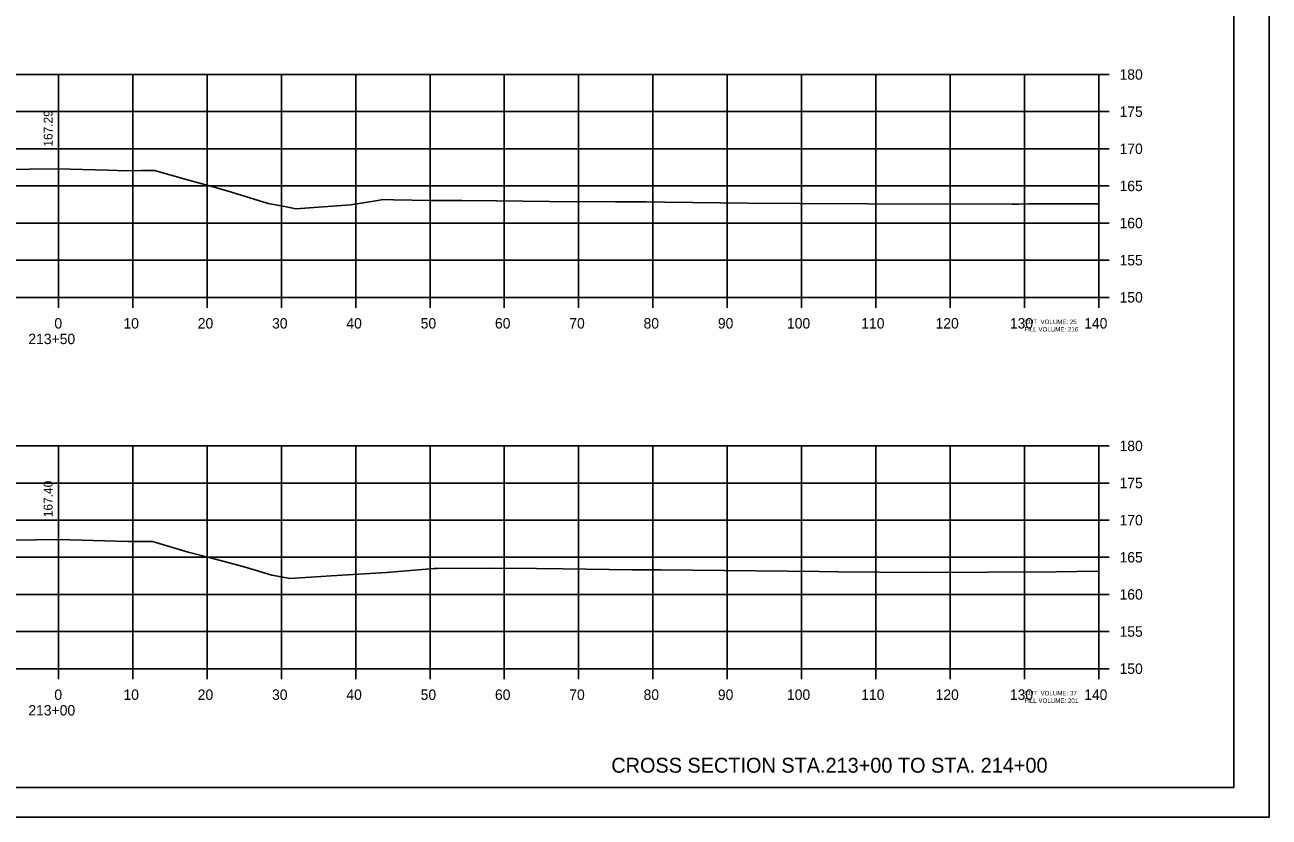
# Model space of a CAD drawing. Extents: x 1368503 to 1373085, y 379840 to 381833.
# Drawn here: x 1368668.5 to 1368836, y 381192.7 to 381299.4 of the extents above; entities that cross this region are included whole.
import ezdxf

# ---------------------------------------------------------------- set-up
doc = ezdxf.new("R2010")
doc.units = 0
for name, color, linetype in [('S_BRIDGE', 7, 'Continuous'), ('S_EDGE_PAVEMENT', 7, 'Continuous'), ('S_MISC_BOUNDARY', 7, 'Continuous'), ('S_PHOTO_CENTERS', 7, 'Continuous'), ('S_PHOTO_NOTES', 7, 'Continuous'), ('S_TRAILS', 7, 'Continuous'), ('S_TRAILS_ANNOT', 7, 'Continuous'), ('S_TREE', 7, 'Continuous')]:
    doc.layers.add(name, color=color, linetype=linetype)

msp = doc.modelspace()

# ---------------------------------------------------------------- linework, layer by layer
at = {"layer": 'S_BRIDGE'}
for q in [(1368831.24, 381402.18), (1368515.06, 381196.72)]:
    msp.add_line((1368831.24, 381196.72), q, dxfattribs=at)
at = {"layer": 'S_EDGE_PAVEMENT'}
for p, q in [((1368813.06, 381262.72), (1368813.06, 381292.72)), ((1368814.46, 381292.72), (1368813.06, 381292.72)), ((1368814.46, 381287.72), (1368813.06, 381287.72)), ((1368814.46, 381282.72), (1368813.06, 381282.72)), ((1368814.46, 381277.72), (1368813.06, 381277.72)), ((1368814.46, 381272.72), (1368813.06, 381272.72)), ((1368814.46, 381267.72), (1368813.06, 381267.72)), ((1368533.06, 381262.72), (1368813.06, 381262.72)), ((1368673.06, 381261.32), (1368673.06, 381262.72)), ((1368683.06, 381261.32), (1368683.06, 381262.72)), ((1368693.06, 381261.32), (1368693.06, 381262.72)), ((1368703.06, 381261.32), (1368703.06, 381262.72)), ((1368713.06, 381261.32), (1368713.06, 381262.72)), ((1368723.06, 381261.32), (1368723.06, 381262.72)), ((1368733.06, 381261.32), (1368733.06, 381262.72)), ((1368743.06, 381261.32), (1368743.06, 381262.72)), ((1368753.06, 381261.32), (1368753.06, 381262.72)), ((1368763.06, 381261.32), (1368763.06, 381262.72)), ((1368773.06, 381261.32), (1368773.06, 381262.72)), ((1368783.06, 381261.32), (1368783.06, 381262.72)), ((1368793.06, 381261.32), (1368793.06, 381262.72)), ((1368803.06, 381261.32), (1368803.06, 381262.72)), ((1368813.06, 381261.32), (1368813.06, 381262.72)), ((1368814.46, 381262.72), (1368813.06, 381262.72)), ((1368813.06, 381212.72), (1368813.06, 381242.72)), ((1368814.46, 381242.72), (1368813.06, 381242.72)), ((1368814.46, 381237.72), (1368813.06, 381237.72)), ((1368814.46, 381232.72), (1368813.06, 381232.72)), ((1368814.46, 381227.72), (1368813.06, 381227.72)), ((1368814.46, 381222.72), (1368813.06, 381222.72)), ((1368814.46, 381217.72), (1368813.06, 381217.72)), ((1368533.06, 381212.72), (1368813.06, 381212.72)), ((1368673.06, 381211.32), (1368673.06, 381212.72)), ((1368683.06, 381211.32), (1368683.06, 381212.72)), ((1368693.06, 381211.32), (1368693.06, 381212.72)), ((1368703.06, 381211.32), (1368703.06, 381212.72)), ((1368713.06, 381211.32), (1368713.06, 381212.72)), ((1368723.06, 381211.32), (1368723.06, 381212.72)), ((1368733.06, 381211.32), (1368733.06, 381212.72)), ((1368743.06, 381211.32), (1368743.06, 381212.72)), ((1368753.06, 381211.32), (1368753.06, 381212.72)), ((1368763.06, 381211.32), (1368763.06, 381212.72)), ((1368773.06, 381211.32), (1368773.06, 381212.72)), ((1368783.06, 381211.32), (1368783.06, 381212.72)), ((1368793.06, 381211.32), (1368793.06, 381212.72)), ((1368803.06, 381211.32), (1368803.06, 381212.72)), ((1368813.06, 381211.32), (1368813.06, 381212.72)), ((1368814.46, 381212.72), (1368813.06, 381212.72))]:
    msp.add_line(p, q, dxfattribs=at)
at = {"layer": 'S_MISC_BOUNDARY'}
for points in [[(1368665.26, 381279.95), (1368672.95, 381280.01), (1368679.64, 381279.84), (1368682.25, 381279.77), (1368684.17, 381279.79), (1368685.98, 381279.78), (1368690.43, 381278.56), (1368693.89, 381277.61), (1368696.33, 381276.87), (1368701.27, 381275.34), (1368703.5, 381274.93), (1368705.01, 381274.65), (1368708.05, 381274.86), (1368712.42, 381275.18), (1368716.02, 381275.78), (1368716.69, 381275.9), (1368718.18, 381275.86), (1368723.09, 381275.77), (1368727.32, 381275.75), (1368732.04, 381275.71), (1368739.13, 381275.62), (1368748.01, 381275.57), (1368750.79, 381275.59), (1368752.12, 381275.58), (1368754.66, 381275.55), (1368765.83, 381275.42), (1368772.82, 381275.37), (1368781.92, 381275.3), (1368801.47, 381275.28), (1368802.28, 381275.28), (1368803.59, 381275.29), (1368813.06, 381275.32)], [(1368664.11, 381229.98), (1368672.82, 381230.13), (1368674.64, 381230.08), (1368682.38, 381229.86), (1368683.53, 381229.84), (1368685.72, 381229.86), (1368690.53, 381228.43), (1368693.5, 381227.64), (1368698.03, 381226.42), (1368701.77, 381225.33), (1368703.51, 381224.99), (1368704.21, 381224.86), (1368709.76, 381225.23), (1368717.19, 381225.67), (1368723.61, 381226.19), (1368723.83, 381226.21), (1368724.05, 381226.22), (1368730.95, 381226.27), (1368737.38, 381226.23), (1368741, 381226.17), (1368750.26, 381226.04), (1368754.13, 381226.02), (1368775.45, 381225.8), (1368778.02, 381225.78), (1368789.03, 381225.67), (1368798.07, 381225.7), (1368807.32, 381225.74), (1368812.89, 381225.83), (1368813.06, 381225.83)]]:
    msp.add_lwpolyline(points, dxfattribs=at)
at = {"layer": 'S_PHOTO_CENTERS'}
for p, q in [((1368533.06, 381292.72), (1368813.06, 381292.72)), ((1368673.06, 381262.72), (1368673.06, 381292.72)), ((1368683.06, 381262.72), (1368683.06, 381292.72)), ((1368693.06, 381262.72), (1368693.06, 381292.72)), ((1368703.06, 381262.72), (1368703.06, 381292.72)), ((1368713.06, 381262.72), (1368713.06, 381292.72)), ((1368723.06, 381262.72), (1368723.06, 381292.72)), ((1368733.06, 381262.72), (1368733.06, 381292.72)), ((1368743.06, 381262.72), (1368743.06, 381292.72)), ((1368753.06, 381262.72), (1368753.06, 381292.72)), ((1368763.06, 381262.72), (1368763.06, 381292.72)), ((1368773.06, 381262.72), (1368773.06, 381292.72)), ((1368783.06, 381262.72), (1368783.06, 381292.72)), ((1368793.06, 381262.72), (1368793.06, 381292.72)), ((1368803.06, 381262.72), (1368803.06, 381292.72)), ((1368813.06, 381262.72), (1368813.06, 381292.72)), ((1368533.06, 381287.72), (1368813.06, 381287.72)), ((1368533.06, 381282.72), (1368813.06, 381282.72)), ((1368533.06, 381277.72), (1368813.06, 381277.72)), ((1368533.06, 381272.72), (1368813.06, 381272.72)), ((1368533.06, 381267.72), (1368813.06, 381267.72)), ((1368533.06, 381262.72), (1368813.06, 381262.72)), ((1368533.06, 381242.72), (1368813.06, 381242.72)), ((1368673.06, 381212.72), (1368673.06, 381242.72)), ((1368683.06, 381212.72), (1368683.06, 381242.72)), ((1368693.06, 381212.72), (1368693.06, 381242.72)), ((1368703.06, 381212.72), (1368703.06, 381242.72)), ((1368713.06, 381212.72), (1368713.06, 381242.72)), ((1368723.06, 381212.72), (1368723.06, 381242.72)), ((1368733.06, 381212.72), (1368733.06, 381242.72)), ((1368743.06, 381212.72), (1368743.06, 381242.72)), ((1368753.06, 381212.72), (1368753.06, 381242.72)), ((1368763.06, 381212.72), (1368763.06, 381242.72)), ((1368773.06, 381212.72), (1368773.06, 381242.72)), ((1368783.06, 381212.72), (1368783.06, 381242.72)), ((1368793.06, 381212.72), (1368793.06, 381242.72)), ((1368803.06, 381212.72), (1368803.06, 381242.72)), ((1368813.06, 381212.72), (1368813.06, 381242.72)), ((1368533.06, 381237.72), (1368813.06, 381237.72)), ((1368533.06, 381232.72), (1368813.06, 381232.72)), ((1368533.06, 381227.72), (1368813.06, 381227.72)), ((1368533.06, 381222.72), (1368813.06, 381222.72)), ((1368533.06, 381217.72), (1368813.06, 381217.72)), ((1368533.06, 381212.72), (1368813.06, 381212.72))]:
    msp.add_line(p, q, dxfattribs=at)
at = {"layer": 'S_PHOTO_NOTES'}
msp.add_line((1368502.66, 381192.74), (1368835.99, 381192.74), dxfattribs=at)
for points in [[(1368502.65, 381406.07), (1368835.99, 381406.07), (1368835.99, 381192.74), (1368502.65, 381192.74)], [(1368748.98, 381402.18), (1368748.98, 381392.3), (1368784.71, 381392.3), (1368784.71, 381389.38), (1368807.91, 381389.38), (1368807.91, 381365.05), (1368831.24, 381365.05), (1368831.24, 381196.72), (1368515.06, 381196.72), (1368515.06, 381402.18)]]:
    msp.add_lwpolyline(points, close=True, dxfattribs=at)

# ---------------------------------------------------------------- texts
at = {"layer": 'S_TRAILS'}
for s, height, p in [('180', 1.4, (1368815.86, 381292.02)), ('175', 1.4, (1368815.86, 381287.02)), ('170', 1.4, (1368815.86, 381282.02)), ('165', 1.4, (1368815.86, 381277.02)), ('160', 1.4, (1368815.86, 381272.02)), ('155', 1.4, (1368815.86, 381267.02)), ('150', 1.4, (1368815.86, 381262.02)), ('0', 1.4, (1368672.5, 381258.52)), ('10', 1.4, (1368681.8, 381258.52)), ('20', 1.4, (1368691.8, 381258.52)), ('30', 1.4, (1368701.8, 381258.52)), ('40', 1.4, (1368711.8, 381258.52)), ('50', 1.4, (1368721.8, 381258.52)), ('60', 1.4, (1368731.8, 381258.52)), ('70', 1.4, (1368741.8, 381258.52)), ('80', 1.4, (1368751.8, 381258.52)), ('90', 1.4, (1368761.8, 381258.52)), ('100', 1.4, (1368771.1, 381258.52)), ('110', 1.4, (1368781.1, 381258.52)), ('120', 1.4, (1368791.1, 381258.52)), ('130', 1.4, (1368801.1, 381258.52)), ('CUT  VOLUME: 25', 0.6, (1368803.06, 381259.12)), ('FILL VOLUME: 216', 0.6, (1368803.06, 381258.12)), ('140', 1.4, (1368811.1, 381258.52)), ('213+50', 1.4, (1368669, 381256.42)), ('180', 1.4, (1368815.86, 381242.02)), ('175', 1.4, (1368815.86, 381237.02)), ('170', 1.4, (1368815.86, 381232.02)), ('165', 1.4, (1368815.86, 381227.02)), ('160', 1.4, (1368815.86, 381222.02)), ('155', 1.4, (1368815.86, 381217.02)), ('150', 1.4, (1368815.86, 381212.02)), ('0', 1.4, (1368672.5, 381208.52)), ('10', 1.4, (1368681.8, 381208.52)), ('20', 1.4, (1368691.8, 381208.52)), ('30', 1.4, (1368701.8, 381208.52)), ('40', 1.4, (1368711.8, 381208.52)), ('50', 1.4, (1368721.8, 381208.52)), ('60', 1.4, (1368731.8, 381208.52)), ('70', 1.4, (1368741.8, 381208.52)), ('80', 1.4, (1368751.8, 381208.52)), ('90', 1.4, (1368761.8, 381208.52)), ('100', 1.4, (1368771.1, 381208.52)), ('110', 1.4, (1368781.1, 381208.52)), ('120', 1.4, (1368791.1, 381208.52)), ('130', 1.4, (1368801.1, 381208.52)), ('140', 1.4, (1368811.1, 381208.52)), ('CUT  VOLUME: 37', 0.6, (1368803.06, 381209.12)), ('FILL VOLUME: 201', 0.6, (1368803.06, 381208.12)), ('213+00', 1.4, (1368669, 381206.42))]:
    msp.add_text(s, height=height, dxfattribs=at).set_placement(p)
at = {"layer": 'S_TRAILS_ANNOT'}
for s, p in [('167.29', (1368672.26, 381283.01)), ('167.40', (1368672.26, 381233.12))]:
    msp.add_text(s, height=1.2, rotation=90, dxfattribs=at).set_placement(p)
at = {"layer": 'S_TREE'}
msp.add_text('CROSS SECTION STA.213+00 TO STA. 214+00', height=2, dxfattribs=at).set_placement((1368747.46, 381198.72))

doc.saveas('drawing.dxf')
